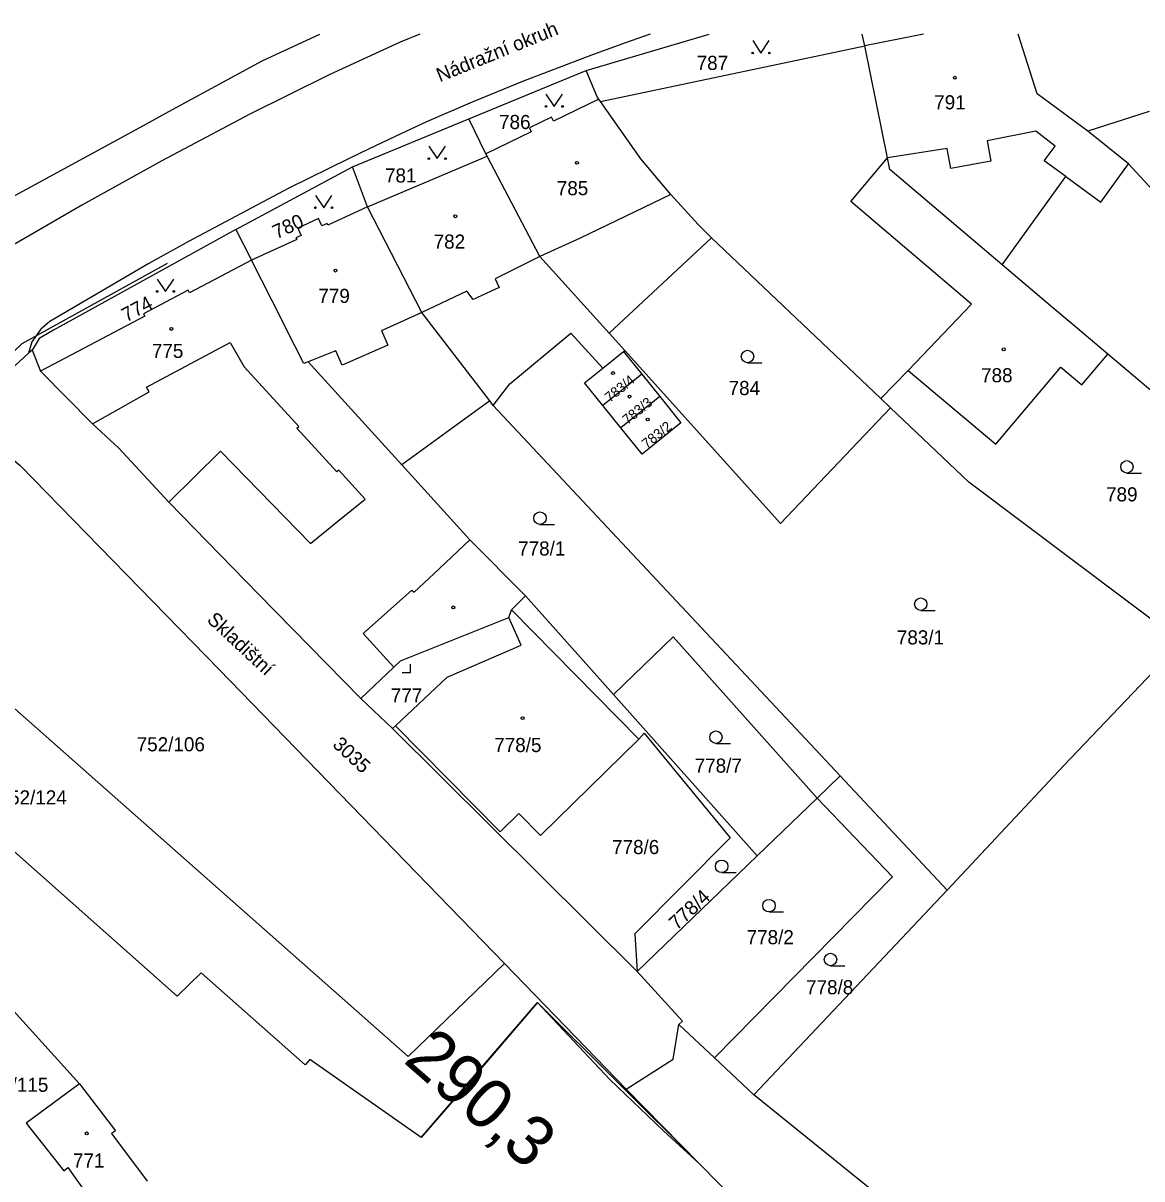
# Model space of a CAD drawing. Extents: x -496682 to -495907, y -1088575 to -1088018.
# Drawn here: x -496531.3 to -496396.5, y -1088157.4 to -1088018.2 of the extents above; entities that cross this region are included whole.
import ezdxf

# ---------------------------------------------------------------- set-up
doc = ezdxf.new("R2010")
doc.units = 0
for name, color, linetype in [('Hranice parcel', 7, 'Continuous'), ('Parcelní čísla', 7, 'Continuous'), ('Pop  PČ popisy', 7, 'Continuous'), ('Vnitřní kresba', 7, 'Continuous'), ('Vrstva 54', 7, 'Continuous'), ('Vrstva 7', 7, 'Continuous'), ('Značky budov', 7, 'Continuous'), ('Značky kultur', 7, 'Continuous')]:
    doc.layers.add(name, color=color, linetype=linetype)

msp = doc.modelspace()

# ---------------------------------------------------------------- linework, layer by layer
at = {"layer": 'Hranice parcel'}
for p, q in [((-496463.43, -1088023.85), (-496448.62, -1088019.49)), ((-496429.86, -1088020.9), (-496430.15, -1088019.49)), ((-496461.7, -1088027.6), (-496429.86, -1088020.9)), ((-496477.56, -1088029.71), (-496463.43, -1088023.85)), ((-496461.7, -1088027.6), (-496461.89, -1088027.33)), ((-496491.56, -1088035.46), (-496477.56, -1088029.71)), ((-496475.51, -1088033.91), (-496477.56, -1088029.71)), ((-496489.76, -1088040.29), (-496475.36, -1088034.2)), ((-496475.36, -1088034.2), (-496475.51, -1088033.91)), ((-496505.64, -1088043.04), (-496491.56, -1088035.46)), ((-496489.76, -1088040.29), (-496491.56, -1088035.46)), ((-496393.29, -1088040.33), (-496398.07, -1088035.13)), ((-496505.64, -1088043.04), (-496503.75, -1088046.73)), ((-496448.33, -1088044.01), (-496460.66, -1088055.5)), ((-496427.9, -1088063.4), (-496448.33, -1088044.01)), ((-496458.78, -1088057.6), (-496460.66, -1088055.5)), ((-496530.21, -1088056.55), (-496530.6, -1088057.93)), ((-496529.32, -1088056.14), (-496530.18, -1088057.55)), ((-496530.6, -1088057.93), (-496537.16, -1088063.89)), ((-496530.18, -1088057.55), (-496530.6, -1088057.93)), ((-496530.18, -1088057.55), (-496529.16, -1088060.1)), ((-496461.41, -1088059.72), (-496458.93, -1088057.71)), ((-496458.93, -1088057.71), (-496458.78, -1088057.6)), ((-496458.93, -1088057.71), (-496456.73, -1088060.44)), ((-496378.15, -1088076.93), (-496400.58, -1088058.06)), ((-496456.73, -1088060.44), (-496461.42, -1088064.22)), ((-496456.73, -1088060.44), (-496454.53, -1088063.16)), ((-496475.05, -1088063.65), (-496485.62, -1088071.37)), ((-496474.62, -1088064.21), (-496475.05, -1088063.65)), ((-496454.53, -1088063.16), (-496459.23, -1088066.92)), ((-496426.74, -1088064.5), (-496427.9, -1088063.4)), ((-496432.83, -1088108.84), (-496474.62, -1088064.21)), ((-496459.23, -1088066.92), (-496461.42, -1088064.22)), ((-496472.42, -1088088.85), (-496470.72, -1088087.17)), ((-496470.72, -1088087.17), (-496460.13, -1088099.06)), ((-496472.74, -1088089.78), (-496472.42, -1088088.85)), ((-496472.42, -1088088.85), (-496457.09, -1088104.41)), ((-496490.59, -1088099.54), (-496486.76, -1088103.13)), ((-496442.81, -1088118.48), (-496460.13, -1088099.06)), ((-496486.76, -1088103.13), (-496486.4, -1088102.8)), ((-496486.76, -1088103.13), (-496457.27, -1088132.43)), ((-496435.61, -1088111.52), (-496432.83, -1088108.84)), ((-496432.83, -1088108.84), (-496419.93, -1088122.62)), ((-496435.61, -1088111.52), (-496442.81, -1088118.48)), ((-496442.81, -1088118.48), (-496457.27, -1088132.43)), ((-496419.93, -1088122.62), (-496443.22, -1088147.27)), ((-496473.26, -1088131.47), (-496458.59, -1088146.6)), ((-496447.95, -1088142.83), (-496452.25, -1088138.8)), ((-496443.22, -1088147.27), (-496447.95, -1088142.83)), ((-496458.59, -1088146.6), (-496449.81, -1088155.53)), ((-496442.49, -1088162.96), (-496449.81, -1088155.53))]:
    msp.add_line(p, q, dxfattribs=at)
for points in [[(-496483.48, -1088019.49), (-496485.82, -1088020.47), (-496494.39, -1088024.4), (-496503.94, -1088029.11), (-496514.57, -1088034.74), (-496524.1, -1088040.06), (-496538.76, -1088048.54), (-496541.46, -1088044.3)], [(-496538.04, -1088042.05), (-496516.74, -1088030.48), (-496513.69, -1088028.82), (-496502.45, -1088022.72), (-496495.5, -1088019.49)], [(-496455.71, -1088019.49), (-496458.68, -1088020.53), (-496462.8, -1088022.03), (-496471.09, -1088025.21), (-496477.17, -1088027.68), (-496482.67, -1088030.05), (-496486.45, -1088031.8), (-496489.58, -1088033.31), (-496492.04, -1088034.49), (-496499.24, -1088038.05), (-496511.35, -1088044.46), (-496516.12, -1088047.12), (-496528.03, -1088054.1), (-496529.12, -1088055.01), (-496530.21, -1088056.55)], [(-496422.76, -1088019.49), (-496429.86, -1088020.9)], [(-496398.07, -1088035.13), (-496402.96, -1088031.19), (-496409.09, -1088026.67), (-496411.38, -1088019.49)], [(-496413.29, -1088047.29), (-496426.84, -1088035.81), (-496427.12, -1088034.4), (-496429.86, -1088020.9)], [(-496461.89, -1088027.33), (-496462.08, -1088027.04), (-496463.43, -1088023.85)], [(-496461.89, -1088027.33), (-496467.37, -1088029.97), (-496467.6, -1088029.48), (-496470.27, -1088030.77), (-496470.03, -1088031.26), (-496475.51, -1088033.91)], [(-496448.33, -1088044.01), (-496449.92, -1088042.41), (-496453.22, -1088038.81), (-496456.83, -1088034.51), (-496461.7, -1088027.6)], [(-496460.66, -1088055.5), (-496468.99, -1088046.29), (-496475.36, -1088034.2)], [(-496413.29, -1088047.29), (-496405.62, -1088036.65), (-496401.42, -1088039.72), (-496398.07, -1088035.13)], [(-496489.76, -1088040.29), (-496494.55, -1088042.49), (-496494.62, -1088042.28), (-496495.28, -1088042.59), (-496495.68, -1088041.71), (-496498.16, -1088042.85), (-496497.76, -1088043.73), (-496498.39, -1088044.02), (-496498.3, -1088044.22), (-496503.75, -1088046.73)], [(-496475.05, -1088063.65), (-496483.23, -1088053.04), (-496489.76, -1088040.29)], [(-496505.64, -1088043.04), (-496527.61, -1088055.16), (-496529.32, -1088056.14)], [(-496503.75, -1088046.73), (-496511.2, -1088050.65), (-496511.36, -1088050.35), (-496516.74, -1088053.18), (-496516.58, -1088053.48), (-496529.16, -1088060.1)], [(-496485.62, -1088071.37), (-496496.9, -1088058.96), (-496497.43, -1088059.17), (-496499.6, -1088054.9), (-496500.03, -1088054.06), (-496503.75, -1088046.73)], [(-496400.58, -1088058.06), (-496404.74, -1088054.5), (-496407.19, -1088052.46), (-496413.29, -1088047.29)], [(-496474.62, -1088064.21), (-496472.61, -1088061.62), (-496465.26, -1088055.5), (-496461.41, -1088059.72)], [(-496426.74, -1088064.5), (-496440.01, -1088078.44), (-496458.78, -1088057.6)], [(-496427.9, -1088063.4), (-496424.63, -1088059.99), (-496414.08, -1088068.89), (-496406.22, -1088059.61), (-496403.7, -1088061.75), (-496400.58, -1088058.06)], [(-496461.42, -1088064.22), (-496463.62, -1088061.5), (-496461.41, -1088059.72)], [(-496529.16, -1088060.1), (-496522.91, -1088066.43), (-496519.74, -1088069.36), (-496513.72, -1088075.89), (-496502.91, -1088086.95), (-496490.59, -1088099.54)], [(-496454.53, -1088063.16), (-496452.01, -1088066.3), (-496456.69, -1088070.07), (-496459.23, -1088066.92)], [(-496391.63, -1088092.77), (-496417.3, -1088073.45), (-496426.74, -1088064.5)], [(-496539.03, -1088065.6), (-496535.97, -1088067.83), (-496531.62, -1088071.46), (-496507.63, -1088096.03), (-496473.26, -1088131.47)], [(-496470.72, -1088087.17), (-496477.42, -1088080.39), (-496485.62, -1088071.37)], [(-496559, -1088077.16), (-496484.87, -1088142.67), (-496473.26, -1088131.47)], [(-496449.81, -1088155.53), (-496454.1, -1088151.6), (-496460.56, -1088145.42), (-496469.27, -1088136.13), (-496476.41, -1088144.48), (-496483.29, -1088152.42), (-496496.71, -1088143.01), (-496497.27, -1088143.67), (-496509.81, -1088132.58), (-496512.72, -1088135.39), (-496534.24, -1088116.3), (-496558.95, -1088090.57), (-496566.25, -1088088.69), (-496568.44, -1088087.46), (-496570.32, -1088085.3), (-496571.02, -1088084.13)], [(-496490.59, -1088099.54), (-496486.61, -1088095.77), (-496485.8, -1088095), (-496472.74, -1088089.78)], [(-496486.4, -1088102.8), (-496480.19, -1088096.97), (-496471.27, -1088093.11), (-496472.74, -1088089.78)], [(-496460.13, -1088099.06), (-496452.93, -1088092.09), (-496435.61, -1088111.52)], [(-496419.93, -1088122.62), (-496405.88, -1088107.6), (-496393.38, -1088094.52)], [(-496486.4, -1088102.8), (-496473.77, -1088115.6), (-496471.54, -1088113.39), (-496468.92, -1088116.03), (-496457.09, -1088104.41)], [(-496457.09, -1088104.41), (-496456.42, -1088103.71), (-496446.07, -1088116.33), (-496457.55, -1088127.89), (-496457.27, -1088132.43)], [(-496447.95, -1088142.83), (-496426.52, -1088121), (-496435.61, -1088111.52)], [(-496457.27, -1088132.43), (-496451.82, -1088138.41), (-496452.25, -1088138.8)], [(-496539.92, -1088143.81), (-496532.42, -1088137.16), (-496524.49, -1088145.94)], [(-496458.59, -1088146.6), (-496452.94, -1088142.96), (-496452.25, -1088138.8)], [(-496524.49, -1088145.94), (-496530.88, -1088150.68), (-496526.37, -1088156.42)], [(-496524.49, -1088145.94), (-496520.15, -1088151.6), (-496520.61, -1088151.95), (-496516.3, -1088157.66)], [(-496395.1, -1088185.29), (-496395.64, -1088185.72), (-496443.22, -1088147.27)], [(-496526.37, -1088156.42), (-496525.89, -1088156.04), (-496521.83, -1088161.73)]]:
    msp.add_lwpolyline(points, dxfattribs=at)
at = {"layer": 'Vnitřní kresba'}
for p, q in [((-496395.59, -1088028.81), (-496402.96, -1088031.19)), ((-496409.24, -1088031.19), (-496415.09, -1088032.36)), ((-496406.9, -1088033), (-496409.24, -1088031.19)), ((-496419.92, -1088033.27), (-496427.12, -1088034.4)), ((-496419.49, -1088035.67), (-496419.92, -1088033.27)), ((-496415.09, -1088032.36), (-496414.65, -1088034.8)), ((-496408.25, -1088034.73), (-496406.9, -1088033)), ((-496431.53, -1088039.64), (-496427.12, -1088034.4)), ((-496414.65, -1088034.8), (-496419.49, -1088035.67)), ((-496405.62, -1088036.65), (-496408.25, -1088034.73)), ((-496453.22, -1088038.81), (-496464.13, -1088044.07)), ((-496417, -1088052.03), (-496431.53, -1088039.64)), ((-496464.13, -1088044.07), (-496468.99, -1088046.29)), ((-496468.99, -1088046.29), (-496474.39, -1088048.97)), ((-496473.91, -1088050.01), (-496477.03, -1088051.45)), ((-496474.39, -1088048.97), (-496473.91, -1088050.01)), ((-496477.79, -1088050.44), (-496483.23, -1088053.04)), ((-496477.03, -1088051.45), (-496477.79, -1088050.44)), ((-496417, -1088052.03), (-496424.63, -1088059.99)), ((-496483.23, -1088053.04), (-496487.92, -1088055.14)), ((-496487.92, -1088055.14), (-496488.09, -1088055.2)), ((-496488.09, -1088055.2), (-496487.32, -1088056.95)), ((-496516.39, -1088062), (-496506.32, -1088056.65)), ((-496487.32, -1088056.95), (-496492.84, -1088059.37)), ((-496493.9, -1088057.78), (-496496.9, -1088058.96)), ((-496493.6, -1088057.63), (-496493.9, -1088057.78)), ((-496492.84, -1088059.37), (-496493.6, -1088057.63)), ((-496522.91, -1088066.43), (-496516.07, -1088062.57)), ((-496516.07, -1088062.57), (-496516.39, -1088062)), ((-496498.27, -1088066.96), (-496498.05, -1088066.76)), ((-496493.45, -1088072.23), (-496498.27, -1088066.96)), ((-496493.23, -1088072.03), (-496493.45, -1088072.23)), ((-496490.07, -1088075.5), (-496493.23, -1088072.03)), ((-496493.33, -1088078.18), (-496490.07, -1088075.5)), ((-496481.79, -1088084.52), (-496477.42, -1088080.39)), ((-496484.13, -1088086.72), (-496481.79, -1088084.52)), ((-496490.3, -1088091.68), (-496484.41, -1088086.46)), ((-496484.41, -1088086.46), (-496484.13, -1088086.72)), ((-496486.61, -1088095.77), (-496490.3, -1088091.68))]:
    msp.add_line(p, q, dxfattribs=at)
for points in [[(-496513.9, -1088047.1), (-496531.42, -1088056.78), (-496539.98, -1088064.95), (-496573.76, -1088084.47), (-496608.65, -1088104.15)], [(-496506.32, -1088056.65), (-496504.65, -1088059.56), (-496498.05, -1088066.76)], [(-496513.72, -1088075.89), (-496507.5, -1088069.73), (-496496.62, -1088080.87), (-496493.33, -1088078.18)]]:
    msp.add_lwpolyline(points, dxfattribs=at)
at = {"layer": 'Vrstva 54'}
msp.add_lwpolyline([(-496483.29, -1088152.42), (-496469.27, -1088136.13), (-496449.81, -1088155.53), (-496442.49, -1088162.96), (-496444.47, -1088165.33), (-496443.2, -1088166.44), (-496448.94, -1088173.01), (-496442.99, -1088178.56), (-496444.11, -1088180.1), (-496428.63, -1088193.79), (-496375.97, -1088240.32)], dxfattribs=at)
at = {"layer": 'Značky budov'}
for centre in [(-496419, -1088024.74), (-496464.53, -1088034.99), (-496479.19, -1088041.43), (-496493.63, -1088047.97), (-496513.4, -1088055), (-496413.11, -1088057.46), (-496460.19, -1088060.32), (-496458.2, -1088063.15), (-496456, -1088065.91), (-496479.44, -1088088.55), (-496471.08, -1088101.89), (-496523.6, -1088151.92)]:
    msp.add_circle(centre, 0.175, dxfattribs=at)
at = {"layer": 'Značky kultur'}
for p, q in [((-496443.99, -1088059.07), (-496442.24, -1088059.07)), ((-496398.27, -1088072.36), (-496396.52, -1088072.36)), ((-496468.99, -1088078.55), (-496467.24, -1088078.55)), ((-496423.11, -1088088.91), (-496421.36, -1088088.91)), ((-496484.6, -1088096.4), (-496484.6, -1088095.4)), ((-496485.6, -1088096.4), (-496484.6, -1088096.4)), ((-496447.79, -1088104.94), (-496446.04, -1088104.94)), ((-496447.09, -1088120.49), (-496445.34, -1088120.49)), ((-496441.39, -1088125.23), (-496439.64, -1088125.23)), ((-496433.99, -1088131.72), (-496432.24, -1088131.72))]:
    msp.add_line(p, q, dxfattribs=at)
for points in [[(-496443.36, -1088020.26), (-496442.36, -1088021.76), (-496441.36, -1088020.26)], [(-496468.27, -1088026.7), (-496467.27, -1088028.2), (-496466.27, -1088026.7)], [(-496482.38, -1088032.98), (-496481.38, -1088034.48), (-496480.38, -1088032.98)], [(-496496.05, -1088038.91), (-496495.05, -1088040.41), (-496494.05, -1088038.91)], [(-496515.11, -1088048.99), (-496514.11, -1088050.49), (-496513.11, -1088048.99)]]:
    msp.add_lwpolyline(points, dxfattribs=at)
for centre, radius in [((-496443.36, -1088021.76), 0.1), ((-496441.36, -1088021.76), 0.1), ((-496468.27, -1088028.2), 0.1), ((-496466.27, -1088028.2), 0.1), ((-496482.38, -1088034.48), 0.1), ((-496480.38, -1088034.48), 0.1), ((-496496.05, -1088040.41), 0.1), ((-496494.05, -1088040.41), 0.1), ((-496515.11, -1088050.49), 0.1), ((-496513.11, -1088050.49), 0.1), ((-496443.99, -1088058.32), 0.75), ((-496398.27, -1088071.61), 0.75), ((-496468.99, -1088077.8), 0.75), ((-496423.11, -1088088.16), 0.75), ((-496447.79, -1088104.19), 0.75), ((-496447.09, -1088119.74), 0.75), ((-496441.39, -1088124.48), 0.75), ((-496433.99, -1088130.97), 0.75)]:
    msp.add_circle(centre, radius, dxfattribs=at)

# ---------------------------------------------------------------- texts
at = {"layer": 'Parcelní čísla'}
for s, p in [('787', (-496450.11, -1088023.8)), ('791', (-496421.49, -1088028.55)), ('786', (-496473.92, -1088030.92)), ('781', (-496487.66, -1088037.36)), ('785', (-496466.96, -1088038.89)), ('782', (-496481.8, -1088045.33)), ('779', (-496495.69, -1088051.87)), ('775', (-496515.75, -1088058.5)), ('788', (-496415.84, -1088061.43)), ('784', (-496446.26, -1088062.97)), ('789', (-496400.78, -1088075.78)), ('778/1', (-496471.62, -1088082.3)), ('783/1', (-496425.99, -1088093.01)), ('777', (-496486.96, -1088100)), ('752/106', (-496517.58, -1088105.89)), ('778/5', (-496474.5, -1088105.98)), ('778/7', (-496450.35, -1088108.46)), ('752/124', (-496534.22, -1088112.29)), ('778/6', (-496460.3, -1088118.27)), ('778/2', (-496444.09, -1088129.13)), ('778/8', (-496436.93, -1088135.16)), ('752/115', (-496536.44, -1088146.91)), ('771', (-496525.26, -1088156.04))]:
    msp.add_text(s, height=1.7, dxfattribs=at).set_placement(p)
for s, height, rotation, p in [('780', 1.7, 25, (-496500.72, -1088044.21)), ('774', 1.7, 28, (-496518.83, -1088054.22)), ('783/4', 1.2, 39, (-496460.58, -1088063.9)), ('783/3', 1.2, 39, (-496458.45, -1088066.59)), ('783/2', 1.2, 39, (-496456.11, -1088069.49)), ('3035', 1.7, 317, (-496494.09, -1088105.21)), ('778/4', 1.7, 43, (-496452.49, -1088127.51))]:
    msp.add_text(s, height=height, rotation=rotation, dxfattribs=at).set_placement(p)
at = {"layer": 'Pop  PČ popisy'}
for s, rotation, p in [('Nádražní okruh', 22, (-496481.05, -1088025.3)), ('Skladištní', 317, (-496509.22, -1088090.18))]:
    msp.add_text(s, height=1.7, rotation=rotation, dxfattribs=at).set_placement(p)
at = {"layer": 'Vrstva 7'}
msp.add_text('290,3', height=6, rotation=318.9438, dxfattribs=at).set_placement((-496485.58, -1088143.27))

doc.saveas('drawing.dxf')
